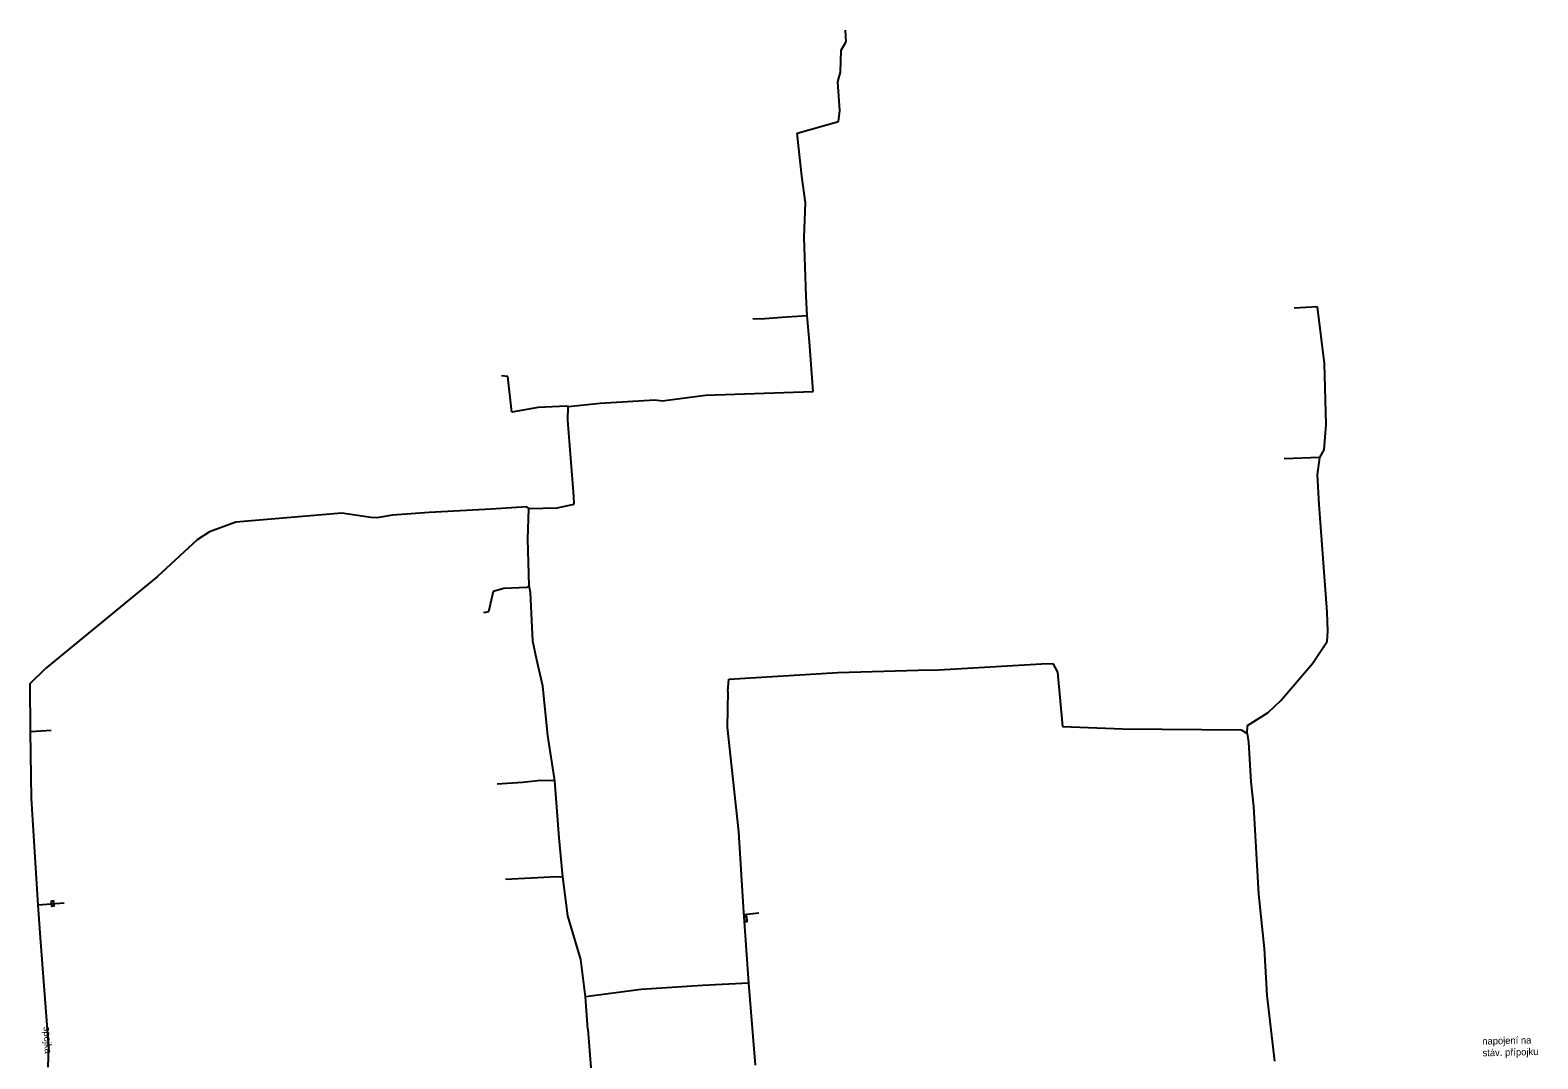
# Model space of a CAD drawing. Extents: x -651943 to -618711, y -1138561 to -1100552.
# Drawn here: x -632855.7 to -632694.7, y -1115689.8 to -1115580 of the extents above; entities that cross this region are included whole.
import ezdxf

# ---------------------------------------------------------------- set-up
doc = ezdxf.new("R2010")
doc.units = 0
for name, color, linetype in [('KT optika', 7, 'Continuous'), ('KT trasa', 7, 'Continuous'), ('KT zařízení', 7, 'Continuous')]:
    doc.layers.add(name, color=color, linetype=linetype)

msp = doc.modelspace()

# ---------------------------------------------------------------- linework, layer by layer
at = {"layer": 'KT optika'}
for p, q in [((-632822.4, -1115631.55), (-632833.72, -1115632.5)), ((-632819.31, -1115632.02), (-632822.4, -1115631.55)), ((-632818.69, -1115632.03), (-632819.31, -1115632.02)), ((-632816.99, -1115631.75), (-632818.69, -1115632.03)), ((-632813.09, -1115631.46), (-632816.99, -1115631.75)), ((-632806.45, -1115631.11), (-632813.09, -1115631.46)), ((-632802.66, -1115630.86), (-632806.45, -1115631.11)), ((-632802.44, -1115631.04), (-632802.66, -1115630.86)), ((-632802.56, -1115634.3), (-632802.44, -1115631.04)), ((-632836.54, -1115633.54), (-632837.85, -1115634.37)), ((-632833.72, -1115632.5), (-632836.54, -1115633.54)), ((-632837.85, -1115634.37), (-632842.11, -1115638.29)), ((-632802.42, -1115639.31), (-632802.56, -1115634.3)), ((-632842.11, -1115638.29), (-632854.04, -1115648.13)), ((-632806.25, -1115639.89), (-632806.76, -1115642.07)), ((-632805.11, -1115639.59), (-632806.25, -1115639.89)), ((-632802.67, -1115639.46), (-632805.11, -1115639.59)), ((-632802.42, -1115639.31), (-632802.67, -1115639.46)), ((-632802.25, -1115640.02), (-632802.42, -1115639.31)), ((-632802, -1115645.2), (-632802.25, -1115640.02)), ((-632806.76, -1115642.07), (-632807.28, -1115642.2)), ((-632801.62, -1115647.05), (-632802, -1115645.2)), ((-632855.69, -1115649.73), (-632854.04, -1115648.13)), ((-632800.96, -1115650.03), (-632801.62, -1115647.05)), ((-632769.44, -1115648.56), (-632760.89, -1115648.29)), ((-632760.89, -1115648.29), (-632758.67, -1115648.26)), ((-632758.67, -1115648.26), (-632747.7, -1115647.64)), ((-632747.7, -1115647.64), (-632746.51, -1115647.6)), ((-632746.51, -1115647.6), (-632745.99, -1115648.51)), ((-632855.64, -1115654.87), (-632855.69, -1115649.73)), ((-632800.43, -1115655.28), (-632800.96, -1115650.03)), ((-632781.19, -1115650.59), (-632781.1, -1115649.26)), ((-632781.1, -1115649.26), (-632769.44, -1115648.56)), ((-632745.99, -1115648.51), (-632745.47, -1115654.31)), ((-632781.19, -1115650.59), (-632781.25, -1115654.39)), ((-632855.64, -1115654.87), (-632853.44, -1115654.7)), ((-632855.56, -1115662.02), (-632855.64, -1115654.87)), ((-632781.25, -1115654.39), (-632780.06, -1115665.58)), ((-632745.47, -1115654.31), (-632739.03, -1115654.57)), ((-632739.03, -1115654.57), (-632726.39, -1115654.67)), ((-632726.39, -1115654.67), (-632725.74, -1115655.06)), ((-632799.67, -1115660.12), (-632800.43, -1115655.28)), ((-632725.74, -1115655.06), (-632725.6, -1115656)), ((-632725.6, -1115656), (-632725.35, -1115660.24)), ((-632803.13, -1115660.3), (-632805.83, -1115660.46)), ((-632801.15, -1115660.08), (-632803.13, -1115660.3)), ((-632799.67, -1115660.12), (-632801.15, -1115660.08)), ((-632799.19, -1115666.21), (-632799.67, -1115660.12)), ((-632725.35, -1115660.24), (-632725.07, -1115662.87)), ((-632854.83, -1115673.35), (-632855.56, -1115662.02)), ((-632725.07, -1115662.87), (-632724.53, -1115672.23)), ((-632780.06, -1115665.58), (-632779.55, -1115673.62)), ((-632798.81, -1115670.37), (-632799.19, -1115666.21)), ((-632802.2, -1115670.51), (-632804.95, -1115670.67)), ((-632800.18, -1115670.42), (-632802.2, -1115670.51)), ((-632798.81, -1115670.37), (-632800.18, -1115670.42)), ((-632798.28, -1115674.54), (-632798.81, -1115670.37)), ((-632724.53, -1115672.23), (-632723.91, -1115678.01)), ((-632854.83, -1115673.35), (-632852.05, -1115673.14)), ((-632854.6, -1115676.87), (-632854.83, -1115673.35)), ((-632779.55, -1115673.62), (-632778.98, -1115681.71)), ((-632796.88, -1115679.19), (-632798.28, -1115674.54)), ((-632777.87, -1115674.26), (-632779.5, -1115674.42)), ((-632853.71, -1115688.54), (-632854.6, -1115676.87)), ((-632723.91, -1115678.01), (-632723.66, -1115683.05)), ((-632796.4, -1115683.2), (-632796.88, -1115679.19)), ((-632783.91, -1115681.97), (-632790.44, -1115682.4)), ((-632778.98, -1115681.71), (-632783.91, -1115681.97)), ((-632790.44, -1115682.4), (-632796.4, -1115683.2)), ((-632723.66, -1115683.05), (-632722.82, -1115690.06)), ((-632853.78, -1115690.68), (-632853.71, -1115688.54))]:
    msp.add_line(p, q, dxfattribs=at)
at = {"layer": 'KT trasa'}
for p, q in [((-632768.68, -1115579.96), (-632768.58, -1115581.25)), ((-632769.18, -1115584.45), (-632769.08, -1115582.1)), ((-632769.08, -1115582.1), (-632768.58, -1115581.25)), ((-632769.46, -1115585.48), (-632769.18, -1115584.45)), ((-632769.22, -1115588.55), (-632769.46, -1115585.48)), ((-632769.39, -1115589.72), (-632769.22, -1115588.55)), ((-632773.79, -1115590.96), (-632769.39, -1115589.72)), ((-632773.28, -1115595.55), (-632773.79, -1115590.96)), ((-632772.91, -1115598.42), (-632773.28, -1115595.55)), ((-632773.04, -1115602.08), (-632772.91, -1115598.42)), ((-632772.83, -1115608.36), (-632773.04, -1115602.09)), ((-632772.71, -1115610.46), (-632772.83, -1115608.36)), ((-632718.25, -1115609.5), (-632720.72, -1115609.64)), ((-632717.47, -1115615.56), (-632718.25, -1115609.5)), ((-632777.25, -1115610.79), (-632778.51, -1115610.83)), ((-632775.44, -1115610.65), (-632777.25, -1115610.79)), ((-632772.71, -1115610.46), (-632775.44, -1115610.65)), ((-632772.48, -1115613.25), (-632772.71, -1115610.46)), ((-632772.1, -1115618.54), (-632772.48, -1115613.25)), ((-632717.29, -1115622.08), (-632717.47, -1115615.56)), ((-632804.69, -1115616.93), (-632805.36, -1115616.89)), ((-632804.25, -1115620.74), (-632804.69, -1115616.93)), ((-632794.81, -1115619.78), (-632788.98, -1115619.44)), ((-632788.98, -1115619.44), (-632788.2, -1115619.54)), ((-632788.2, -1115619.54), (-632783.59, -1115618.93)), ((-632783.59, -1115618.93), (-632772.1, -1115618.54)), ((-632801.45, -1115620.25), (-632804.25, -1115620.74)), ((-632798.44, -1115620.1), (-632801.45, -1115620.25)), ((-632798.23, -1115620.15), (-632798.44, -1115620.1)), ((-632798.28, -1115621.61), (-632798.23, -1115620.15)), ((-632798.23, -1115620.15), (-632794.81, -1115619.78)), ((-632797.65, -1115629.74), (-632798.28, -1115621.61)), ((-632717.52, -1115624.79), (-632717.29, -1115622.08)), ((-632717.98, -1115625.59), (-632721.78, -1115625.74)), ((-632718.25, -1115627.46), (-632717.98, -1115625.59)), ((-632717.98, -1115625.59), (-632717.52, -1115624.79)), ((-632718.06, -1115630.63), (-632718.25, -1115627.46)), ((-632799.41, -1115630.97), (-632797.62, -1115630.57)), ((-632797.62, -1115630.57), (-632797.65, -1115629.74)), ((-632717.19, -1115642.1), (-632718.06, -1115630.63)), ((-632822.4, -1115631.55), (-632833.72, -1115632.5)), ((-632819.31, -1115632.02), (-632822.4, -1115631.55)), ((-632818.69, -1115632.03), (-632819.31, -1115632.02)), ((-632816.99, -1115631.75), (-632818.69, -1115632.03)), ((-632813.09, -1115631.46), (-632816.99, -1115631.75)), ((-632806.45, -1115631.11), (-632813.09, -1115631.46)), ((-632802.66, -1115630.86), (-632806.45, -1115631.11)), ((-632802.44, -1115631.04), (-632802.66, -1115630.86)), ((-632802.56, -1115634.3), (-632802.44, -1115631.04)), ((-632802.44, -1115631.04), (-632799.41, -1115630.97)), ((-632836.54, -1115633.54), (-632837.85, -1115634.37)), ((-632833.72, -1115632.5), (-632836.54, -1115633.54)), ((-632837.85, -1115634.37), (-632842.11, -1115638.29)), ((-632802.42, -1115639.31), (-632802.56, -1115634.3)), ((-632842.11, -1115638.29), (-632854.04, -1115648.13)), ((-632806.25, -1115639.89), (-632806.76, -1115642.07)), ((-632805.11, -1115639.59), (-632806.25, -1115639.89)), ((-632802.67, -1115639.46), (-632805.11, -1115639.59)), ((-632802.42, -1115639.31), (-632802.67, -1115639.46)), ((-632802.25, -1115640.02), (-632802.42, -1115639.31)), ((-632802, -1115645.2), (-632802.25, -1115640.02)), ((-632806.76, -1115642.07), (-632807.28, -1115642.2)), ((-632717.14, -1115644.15), (-632717.19, -1115642.1)), ((-632801.62, -1115647.05), (-632802, -1115645.2)), ((-632717.21, -1115645.26), (-632717.14, -1115644.15)), ((-632718.77, -1115647.6), (-632717.21, -1115645.26)), ((-632855.69, -1115649.73), (-632854.04, -1115648.13)), ((-632800.96, -1115650.03), (-632801.62, -1115647.05)), ((-632769.44, -1115648.56), (-632760.89, -1115648.29)), ((-632760.89, -1115648.29), (-632758.67, -1115648.26)), ((-632758.67, -1115648.26), (-632747.7, -1115647.64)), ((-632747.7, -1115647.64), (-632746.51, -1115647.6)), ((-632746.51, -1115647.6), (-632745.99, -1115648.51)), ((-632722.15, -1115651.56), (-632718.77, -1115647.6)), ((-632855.64, -1115654.87), (-632855.69, -1115649.73)), ((-632800.43, -1115655.28), (-632800.96, -1115650.03)), ((-632781.19, -1115650.59), (-632781.1, -1115649.26)), ((-632781.1, -1115649.26), (-632769.44, -1115648.56)), ((-632745.99, -1115648.51), (-632745.47, -1115654.31)), ((-632781.19, -1115650.59), (-632781.25, -1115654.39)), ((-632723.49, -1115652.83), (-632722.15, -1115651.56)), ((-632725.69, -1115654.21), (-632723.49, -1115652.83)), ((-632855.64, -1115654.87), (-632853.44, -1115654.7)), ((-632855.56, -1115662.02), (-632855.64, -1115654.87)), ((-632781.25, -1115654.39), (-632780.06, -1115665.58)), ((-632745.47, -1115654.31), (-632739.03, -1115654.57)), ((-632739.03, -1115654.57), (-632726.39, -1115654.67)), ((-632726.39, -1115654.67), (-632725.74, -1115655.06)), ((-632725.74, -1115655.06), (-632725.69, -1115654.21)), ((-632799.67, -1115660.12), (-632800.43, -1115655.28)), ((-632725.74, -1115655.06), (-632725.6, -1115656)), ((-632725.6, -1115656), (-632725.35, -1115660.24)), ((-632803.13, -1115660.3), (-632805.83, -1115660.46)), ((-632801.15, -1115660.08), (-632803.13, -1115660.3)), ((-632799.67, -1115660.12), (-632801.15, -1115660.08)), ((-632799.19, -1115666.21), (-632799.67, -1115660.12)), ((-632725.35, -1115660.24), (-632725.07, -1115662.87)), ((-632854.83, -1115673.35), (-632855.56, -1115662.02)), ((-632725.07, -1115662.87), (-632724.53, -1115672.23)), ((-632780.06, -1115665.58), (-632779.55, -1115673.62)), ((-632798.81, -1115670.37), (-632799.19, -1115666.21)), ((-632802.2, -1115670.51), (-632804.95, -1115670.67)), ((-632800.18, -1115670.42), (-632802.2, -1115670.51)), ((-632798.81, -1115670.37), (-632800.18, -1115670.42)), ((-632798.28, -1115674.54), (-632798.81, -1115670.37)), ((-632724.53, -1115672.23), (-632723.91, -1115678.01)), ((-632854.83, -1115673.35), (-632852.05, -1115673.14)), ((-632854.6, -1115676.87), (-632854.83, -1115673.35)), ((-632779.55, -1115673.62), (-632778.98, -1115681.71)), ((-632796.88, -1115679.19), (-632798.28, -1115674.54)), ((-632777.87, -1115674.26), (-632779.5, -1115674.42)), ((-632853.71, -1115688.54), (-632854.6, -1115676.87)), ((-632723.91, -1115678.01), (-632723.66, -1115683.05)), ((-632796.4, -1115683.2), (-632796.88, -1115679.19)), ((-632783.91, -1115681.97), (-632790.44, -1115682.4)), ((-632778.98, -1115681.71), (-632783.91, -1115681.97)), ((-632778.98, -1115681.71), (-632778.27, -1115690.47)), ((-632790.44, -1115682.4), (-632796.4, -1115683.2)), ((-632796.15, -1115686.63), (-632796.4, -1115683.2)), ((-632723.66, -1115683.05), (-632722.82, -1115690.06)), ((-632796.15, -1115686.63), (-632795.54, -1115694.12)), ((-632853.78, -1115690.68), (-632853.71, -1115688.54))]:
    msp.add_line(p, q, dxfattribs=at)
at = {"layer": 'KT zařízení'}
for points in [[(-632853.41, -1115672.93), (-632853.21, -1115672.92), (-632853.18, -1115673.52), (-632853.38, -1115673.53)], [(-632779.4, -1115674.59), (-632779.2, -1115674.58), (-632779.17, -1115675.17), (-632779.37, -1115675.19)]]:
    msp.add_lwpolyline(points, close=True, dxfattribs=at)

# ---------------------------------------------------------------- texts
for s, rotation, p in [('spojka', 272.745, (-632854.26, -1115686.39)), ('napojení na', 1.3575, (-632700.63, -1115688.29)), ('stáv. přípojku', 1.3575, (-632700.6, -1115689.54))]:
    msp.add_text(s, height=0.75, rotation=rotation, dxfattribs=at).set_placement(p)

doc.saveas('drawing.dxf')
